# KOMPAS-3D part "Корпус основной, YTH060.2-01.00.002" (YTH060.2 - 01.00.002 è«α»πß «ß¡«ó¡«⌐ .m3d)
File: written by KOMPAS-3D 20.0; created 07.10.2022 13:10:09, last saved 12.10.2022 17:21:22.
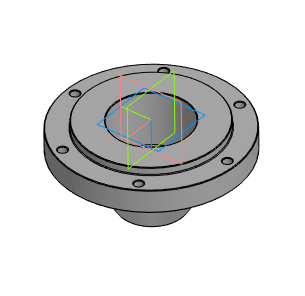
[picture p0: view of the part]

Document properties: Автор: Пользователь Windows; Полное имя файла: D:\информация пользователя\Desktop\ШОРОХ 2022\Насос ХИМия\YTH060.2 С торцевым уплотнением\3D  модель\YTH060.2 Насос сторцевым уплотнением\YTH060.2 - 01.00.002 Корпус основной .m3d

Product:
- Part/product: Корпус основной  | designation YTH060.2-01.00.002
    Материал: Полипропилен  ГОСТ 26996-86 (density 900 kg/m3)
    Масса: 0.346963
    signatures: Разработал Шорохов Д.А.; Проверил Гуляев А.С.; Утвердил Басалов И.С.

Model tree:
1. Операция без истории:1  (labels: 22-0602 Корпус. Средняя часть)
2. Фаска:1  (with: Операция без истории:1)  (labels: Полипропилен  ГОСТ 26996-86)
     Угол = 45; Длина 1 = 0.5; Длина 2 = 0.5

Expressions: 22-0602 Корпус. Средняя часть v5
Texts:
  YTH060.2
